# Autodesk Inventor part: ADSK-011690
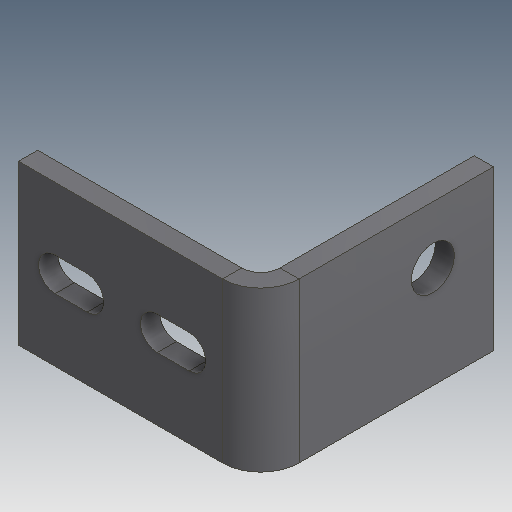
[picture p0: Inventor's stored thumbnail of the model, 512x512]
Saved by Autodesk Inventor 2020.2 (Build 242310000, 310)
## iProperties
Created: 2000-02
Part Number: ADSK-011690
Material: 1.0312 DC05
Document SubType Name: Blech
Designer: sspink
Density: 1 g/cm^3
Appearance: Stahl
Mass: 38.5832 g
Surface Area: 160.21 cm^2
Volume: 38.5832 cm^3
Sheet Metal Rule: Stahlblech 1.0312 - DC05 -   6.0 mm
Flat Pattern Width: 5 cm
Flat Pattern Length: 13.8572 cm
Flat Pattern Area: 69.2858 cm^2
Sheet Metal Width: 50,000 mm
Sheet Metal Length: 138,572 mm
Sheet Metal Area: 6928,584 mm^2
Control State: 0
Master: False
Checked Out: False
Shininess: 0.0
Length Units: 11269
Angle Units: 11279
Time Units: 11290
Mass Units: 11283
Length Display Precision: 3
Angle Display Precision: 2
Compacted: True
Cutlength: 23.25
Material Desc: Material Description goes here
Material_Number: Pearson
Dimensions: 50x73x76 mm
Mass: 0,039 kg
Semi finished: Stahlblech 1.0312 - DC05 -   6.0 mm
VLT_Material: 1.0312 DC05
G_L: 50x138,6 mm
Thickness: 6,000 mm
Density: 0.0
Volumn: 0.0
Area: 0.0
PropertySet Name: Model Information
Author: sspink
Revision Number: -
Title: ADSK-011690
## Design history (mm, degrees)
node "Solide1"
derived "ADSK-011691.ipt"
node "FonctionRepérage2"
feature "Solide1::ADSK-011691.ipt" dims "d0" = 10
node "Corps solides"
node "Corps surfaciques"
feature "Definition1"
other parameters: "Stärke" = 6 (derived), "KFaktor" = 4.4, "Biegeradius" = 6 (= Stärke), "BreiteBiegungsfreistellung" = 6 (= Stärke), "TiefeBiegungsfreistellung" = 3 (= 0.5 x Stärke), "GrößeEckenfreistellung" = 24 (= 4 x Stärke), "AbstandVerbindung" = 0.00508, "MinimalRest" = 12 (= 2 x Stärke), "Übergangsradius" = 6 (= Biegeradius), "JacobiRadiusGröße" = 6 (= Biegeradius), "Abstandsgröße" = 6 (= Stärke), "Abstandsgröße" = 6, "Biegeradius" = 6, "BreiteBiegungsfreistellung" = 6, "GrößeEckenfreistellung" = 24, "JacobiRadiusGröße" = 6, "MinimalRest" = 12, "Stärke" = 6, "TiefeBiegungsfreistellung" = 3, "Übergangsradius" = 6
